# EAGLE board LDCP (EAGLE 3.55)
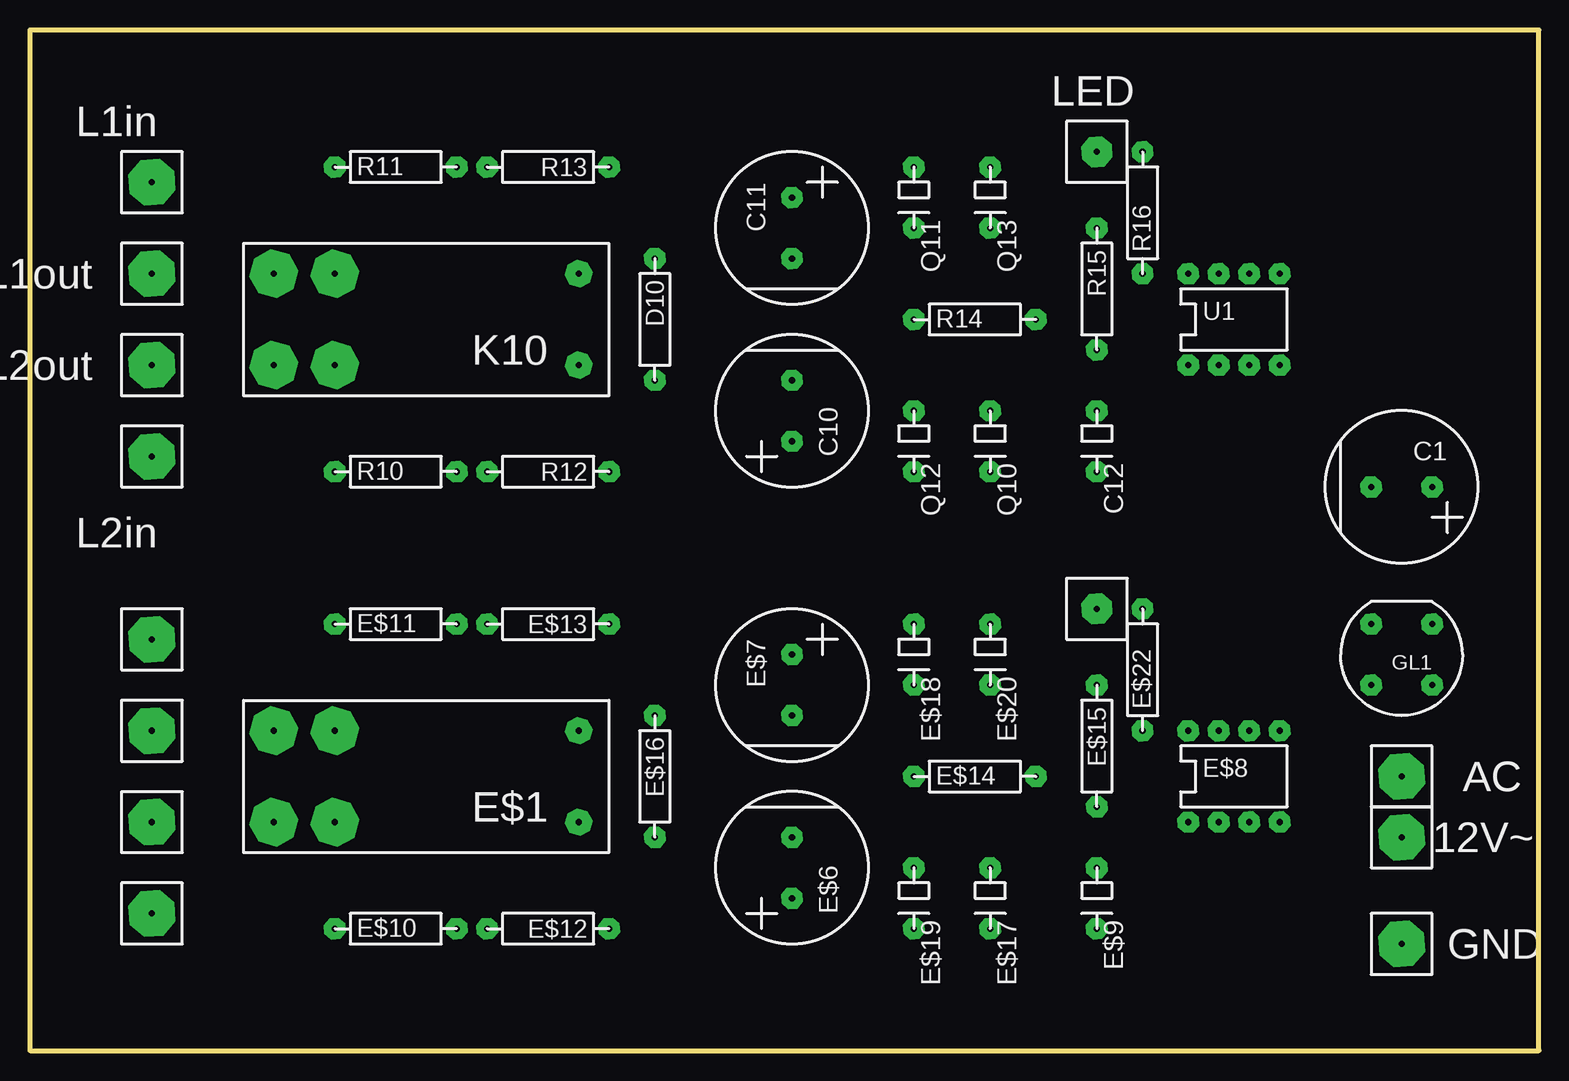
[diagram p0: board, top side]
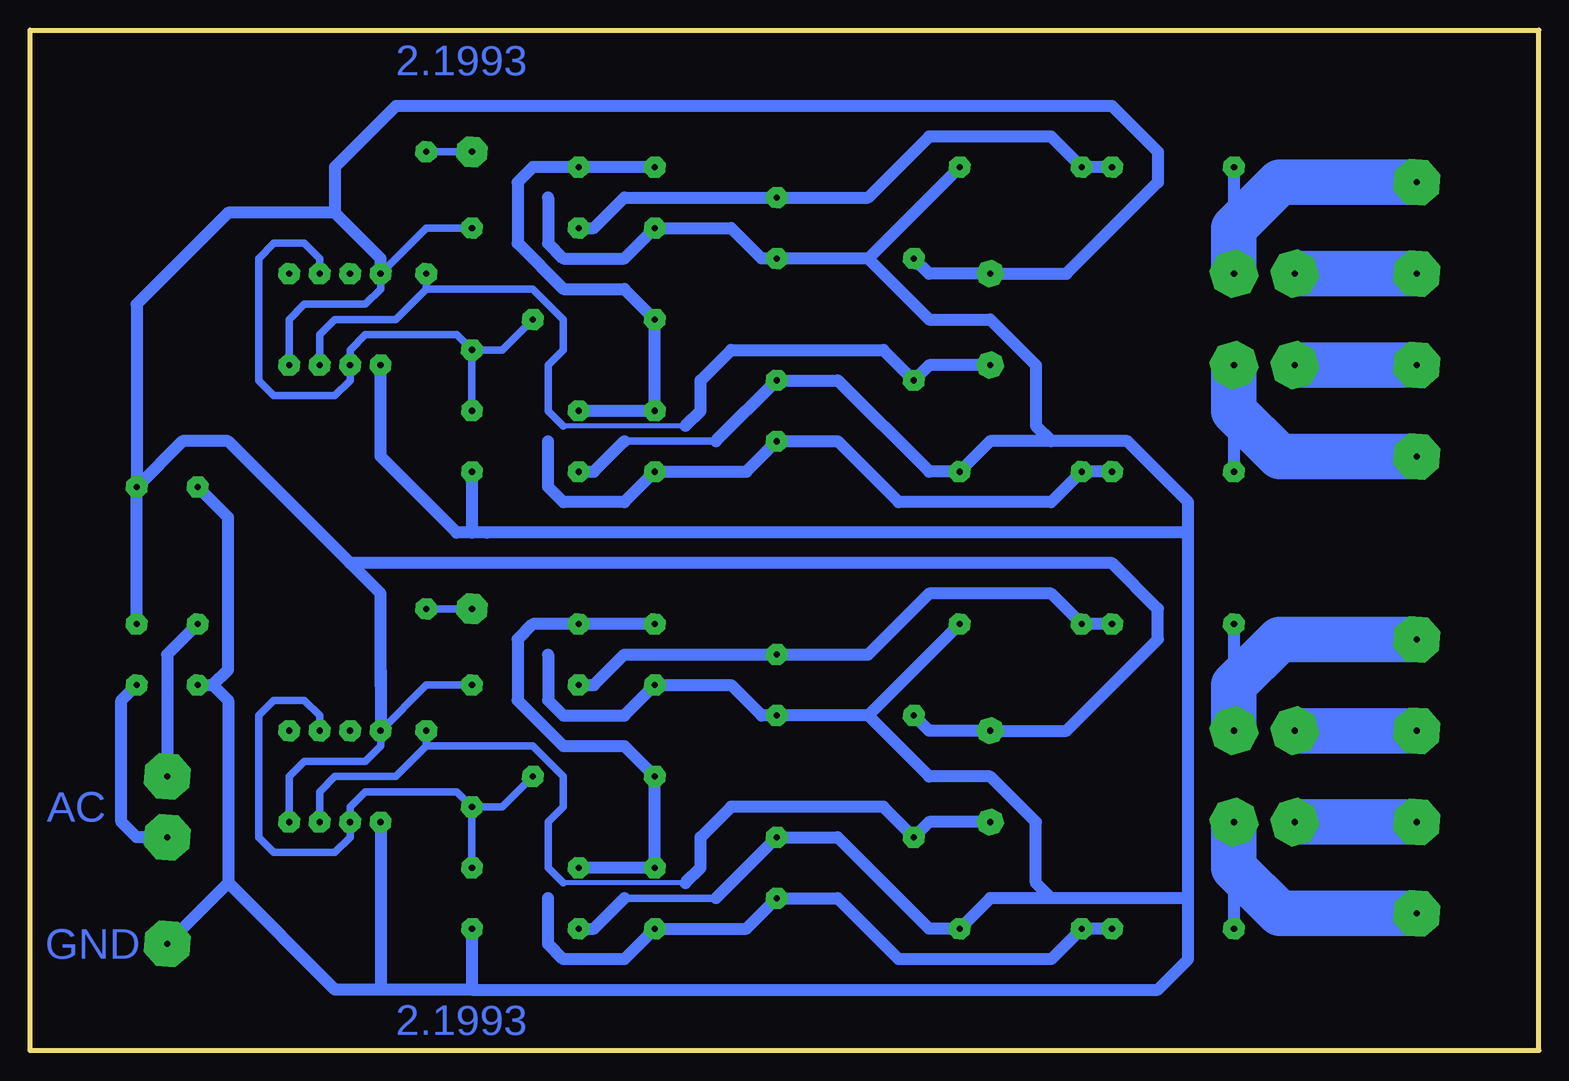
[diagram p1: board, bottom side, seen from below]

Size 125.73 x 85.09 mm. Coordinates in mm from the lower left corner, seen from the top.
Outline: 0,0 125.73,0 125.73,85.09 0,85.09 0,0
Copper layers used: Bottom

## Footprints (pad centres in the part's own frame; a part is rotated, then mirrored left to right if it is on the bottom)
K5_13 = drill 0.508 pad 1.778 octagon:  1.27,5.08;  6.35,5.08
 = drill 0.508 pad 1.778 octagon:  0,0;  5.08,0
0 = drill 0.508 pad 1.778 octagon:  0,0;  10.16,0
L_2S = drill 0.508 pad 2.159 octagon: L1 2.54,2.54; L2 10.16,2.54 | drill 0.508 pad 3.81 octagon: MON1 2.54,22.86; MON2 10.16,22.86;  10.16,27.94;  2.54,27.94
D GROá = drill 0.508 pad 3.81 octagon:  2.54,2.54
L8 = drill 0.508 pad 1.778 octagon:  0,0;  2.54,0;  5.08,0;  7.62,0;  7.62,7.62;  5.08,7.62;  2.54,7.62;  0,7.62
D = drill 0.508 pad 2.54 octagon:  2.54,2.54
EICHRI = drill 0.508 pad 1.778 octagon:  1.27,1.27;  6.35,1.27;  6.35,6.35;  1.27,6.35

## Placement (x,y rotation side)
C1  [K5_13]  118.11,52.07 180 top
C10  [K5_13]  68.58,49.53 90 top
C11  [K5_13]  58.42,72.39 270 top
C12  []  88.9,53.34 270 top
D10  [0]  52.07,66.04 270 top
E$1  [L_2S]  48.26,16.51 90 top
E$2  [D GROá]  7.62,8.89 0 top
E$3  [D GROá]  7.62,31.75 0 top
E$4  [D GROá]  7.62,16.51 0 top
E$5  [D GROá]  7.62,24.13 0 top
E$6  [K5_13]  68.58,11.43 90 top
E$7  [K5_13]  58.42,34.29 270 top
E$8  [L8]  96.52,19.05 0 top
E$9  []  88.9,15.24 270 top
E$10  [0]  25.4,10.16 0 top
E$11  [0]  25.4,35.56 0 top
E$12  [0]  48.26,10.16 180 top
E$13  [0]  48.26,35.56 180 top
E$14  [0]  73.66,22.86 0 top
E$15  [0]  88.9,30.48 270 top
E$16  [0]  52.07,27.94 270 top
E$17  []  80.01,15.24 270 top
E$18  []  73.66,35.56 270 top
E$19  []  73.66,15.24 270 top
E$20  []  80.01,35.56 270 top
E$21  [D GROá]  111.76,6.35 0 top
E$22  [0]  92.71,26.67 90 top
E$24  [D]  86.36,34.29 0 top
E$25  [D]  86.36,72.39 0 top
GL1  [EICHRI]  118.11,36.83 180 top
K10  [L_2S]  48.26,54.61 90 top
Q10  []  80.01,53.34 270 top
Q11  []  73.66,73.66 270 top
Q12  []  73.66,53.34 270 top
Q13  []  80.01,73.66 270 top
R10  [0]  25.4,48.26 0 top
R11  [0]  25.4,73.66 0 top
R12  [0]  48.26,48.26 180 top
R13  [0]  48.26,73.66 180 top
R14  [0]  73.66,60.96 0 top
R15  [0]  88.9,68.58 270 top
R16  [0]  92.71,64.77 90 top
U1  [L8]  96.52,57.15 0 top
X1  [D GROá]  111.76,20.32 0 top
X2  [D GROá]  111.76,15.24 0 top
X10  [D GROá]  7.62,46.99 0 top
X11  [D GROá]  7.62,69.85 0 top
X12  [D GROá]  7.62,54.61 0 top
X13  [D GROá]  7.62,62.23 0 top

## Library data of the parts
C1 C10 C11 E$1-E$7 E$21 E$24 E$25 GL1 K10 X1 X2 X10-X13 = VT
C12 D10 E$8-E$20 E$22 Q10-Q13 R10-R16 U1 = PACKAGES

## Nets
GND: C1. C10. C11. C12. E$6. E$7. E$8. E$9. E$12. E$13. E$17. E$18. E$19. E$20. E$21. GL1. Q10. Q11. Q12. Q13. R12. R13. U1.
N00001: GL1. X1.
N00002: GL1. X2.
N00003: K10.MON1 R10. X10.
N00004: C10. Q10. Q12. R10. R12.
N00005: K10. X12.
N00006: C12. R14. R15. U1.
N00007: K10. X13.
N00008: D10. K10.L1 R16. U1.
N00009: Q10. Q11. Q12. Q13. R14.
N00010: K10.MON2 R11. X11.
N00011: C11. Q11. Q13. R11. R13.
S$1: E$1.MON1 E$2. E$10.
S$2: E$6. E$10. E$12. E$17. E$19.
S$3: E$1. E$4.
S$4: E$8. E$9. E$14. E$15.
S$5: E$1. E$5.
S$6: E$25. R16.
S$7: E$14. E$17. E$18. E$19. E$20.
S$8: E$1.MON2 E$3. E$11.
S$9: E$7. E$11. E$13. E$18. E$20.
S$11: E$1.L1 E$8. E$16. E$22.
S$12: E$22. E$24.
VCC: C1. D10. E$1.L2 E$8. E$15. E$16. GL1. K10.L2 R15. U1.

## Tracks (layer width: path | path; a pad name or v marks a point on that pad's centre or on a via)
GND
  Bottom 0.61: 96.52,57.15 96.52,55.88 | 68.58,50.8 76.2,50.8 | 68.58,12.7 76.2,12.7 | 96.52,19.05 96.52,17.78
  Bottom 1.016: C12. 88.9,43.18 87.63,43.18 | 96.52,57.15 96.52,49.53 90.17,43.18 87.63,43.18 | Q10. 78.74,48.26 76.2,50.8 | 68.58,50.8 C10. 58.42,55.88 50.8,48.26 48.26,48.26 45.72,50.8 40.64,50.8 | 82.55,71.12 82.55,67.31 81.28,66.04 76.2,66.04 Q11. 67.31,68.58 64.77,66.04 C11. 55.88,66.04 | 55.88,66.04 48.26,73.66 | 40.64,50.8 41.91,52.07 41.91,57.15 45.72,60.96 50.8,60.96 55.88,66.04 | 40.64,50.8 34.29,50.8 29.21,45.72 29.21,43.18 | 29.21,43.18 87.63,43.18 | E$17. 78.74,10.16 76.2,12.7 | 68.58,12.7 E$6. 58.42,17.78 50.8,10.16 48.26,10.16 45.72,12.7 40.64,12.7 | 29.21,12.7 29.21,43.18 | C1. 109.22,44.45 109.22,31.75 110.49,30.48 | 111.76,30.48 110.49,30.48 | 110.49,30.48 109.22,29.21 109.22,13.97 | E$21. 109.22,13.97 | 109.22,13.97 100.33,5.08 96.52,5.08 | 96.52,19.05 96.52,5.08 | E$9. 88.9,5.08 | 88.9,5.08 96.52,5.08 | 29.21,12.7 29.21,7.62 31.75,5.08 88.9,5.08 | 29.21,12.7 40.64,12.7 | 40.64,12.7 41.91,13.97 41.91,19.05 45.72,22.86 50.8,22.86 55.88,27.94 | 82.55,33.02 82.55,29.21 81.28,27.94 76.2,27.94 E$18. 67.31,30.48 64.77,27.94 E$7. 55.88,27.94 | 48.26,35.56 55.88,27.94
N00001
  Bottom 1.016: 111.76,35.56 114.3,33.02 X1.
N00002
  Bottom 1.016: X2. 116.84,17.78 118.11,19.05 118.11,29.21 GL1.
N00003
  Bottom 1.016: K10.MON1 25.4,48.26
  Bottom 3.81: X10. 21.59,49.53 25.4,53.34 K10.MON1
N00004
  Bottom 1.016: R10. R12. 40.64,45.72 53.34,45.72 58.42,50.8 63.5,50.8 66.04,48.26 Q12. 76.2,45.72 81.28,45.72 82.55,46.99 82.55,50.8
N00005
  Bottom 3.81: X12. K10.
N00006
  Bottom 0.61: 101.6,64.77 101.6,66.04 102.87,67.31 105.41,67.31 106.68,66.04 106.68,55.88 105.41,54.61 100.33,54.61 99.06,55.88 99.06,57.15 99.06,58.42 97.79,59.69 90.17,59.69 R15. | R14. 86.36,58.42 R15. | R15. 88.9,53.34
N00007
  Bottom 3.81: X13. 20.32,64.77
N00008
  Bottom 0.406: 71.12,52.07 81.28,52.07
  Bottom 0.61: 101.6,57.15 101.6,59.69 100.33,60.96 95.25,60.96 92.71,63.5 | 92.71,63.5 83.82,63.5 81.28,60.96 81.28,58.42 82.55,57.15 82.55,53.34 81.28,52.07 | 92.71,63.5 92.71,64.77
  Bottom 1.016: 71.12,52.07 69.85,53.34 69.85,55.88 67.31,58.42 54.61,58.42 D10. 50.8,57.15 K10.L1
N00009
  Bottom 1.016: 73.66,73.66 80.01,73.66 83.82,73.66 85.09,72.39 85.09,67.31 81.28,63.5 76.2,63.5 73.66,60.96 73.66,53.34 80.01,53.34
N00010
  Bottom 1.016: 25.4,73.66 K10.MON2
  Bottom 3.81: X11. 21.59,72.39 25.4,68.58 K10.MON2
N00011
  Bottom 1.016: R11. R13. 40.64,76.2 50.8,76.2 55.88,71.12 63.5,71.12 76.2,71.12 78.74,68.58 Q13.
S$1
  Bottom 1.016: E$1.MON1 25.4,10.16
  Bottom 3.81: E$2. 21.59,11.43 25.4,15.24 E$1.MON1
S$2
  Bottom 1.016: E$10. E$12. 40.64,7.62 53.34,7.62 58.42,12.7 63.5,12.7 66.04,10.16 E$19. 76.2,7.62 81.28,7.62 82.55,8.89 82.55,12.7
S$3
  Bottom 3.81: E$4. E$1.
S$4
  Bottom 0.61: 101.6,26.67 101.6,27.94 102.87,29.21 105.41,29.21 106.68,27.94 106.68,17.78 105.41,16.51 100.33,16.51 99.06,17.78 99.06,19.05 99.06,20.32 97.79,21.59 90.17,21.59 E$15. | E$14. 86.36,20.32 E$15. | E$15. 88.9,15.24
S$5
  Bottom 3.81: E$5. 20.32,26.67
S$6
  Bottom 0.61: E$25. R16.
S$7
  Bottom 1.016: 73.66,35.56 80.01,35.56 83.82,35.56 85.09,34.29 85.09,29.21 81.28,25.4 76.2,25.4 73.66,22.86 73.66,15.24 80.01,15.24
S$8
  Bottom 1.016: 25.4,35.56 E$1.MON2
  Bottom 3.81: E$3. 21.59,34.29 25.4,30.48 E$1.MON2
S$9
  Bottom 1.016: E$11. E$13. 40.64,38.1 50.8,38.1 55.88,33.02 63.5,33.02 76.2,33.02 78.74,30.48 E$20.
S$11
  Bottom 0.406: 71.12,13.97 81.28,13.97
  Bottom 0.61: 101.6,19.05 101.6,21.59 100.33,22.86 95.25,22.86 92.71,25.4 | 92.71,25.4 83.82,25.4 81.28,22.86 81.28,20.32 82.55,19.05 82.55,15.24 81.28,13.97 | 92.71,25.4 92.71,26.67
  Bottom 1.016: E$1.L1 50.8,19.05 E$16. 54.61,20.32 67.31,20.32 69.85,17.78 69.85,15.24 71.12,13.97
S$12
  Bottom 0.61: E$24. E$22.
VCC
  Bottom 0.61: 88.9,30.48 92.71,30.48 E$8. 96.52,25.4 97.79,24.13 102.87,24.13 104.14,22.86 104.14,19.05 | 88.9,68.58 92.71,68.58 U1. 96.52,63.5 97.79,62.23 102.87,62.23 104.14,60.96 104.14,57.15
  Bottom 1.016: 52.07,27.94 50.8,26.67 E$1.L2 39.37,26.67 31.75,34.29 31.75,36.83 35.56,40.64 99.06,40.64 | 96.52,30.48 96.52,31.75 | 99.06,40.64 109.22,50.8 113.03,50.8 116.84,46.99 | U1. 96.52,66.04 100.33,69.85 | 116.84,35.56 116.84,46.99 | 116.84,43.18 116.84,46.99 | 100.33,69.85 109.22,69.85 116.84,62.23 116.84,46.99 | 96.52,31.75 E$8. | 96.52,31.75 96.52,38.1 99.06,40.64 | 52.07,66.04 50.8,64.77 K10.L2 39.37,64.77 31.75,72.39 31.75,74.93 35.56,78.74 95.25,78.74 100.33,73.66 100.33,69.85

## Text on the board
Bottom: 2.1993 | AC | GND | 2.1993
tPlace: LED | L1in | L1out | L2out | L2in | AC | 12V~ | GND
